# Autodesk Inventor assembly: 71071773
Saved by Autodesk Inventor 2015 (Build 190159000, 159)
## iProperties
Created: 2019-12
Part Number: 71071773
Checked By: TraceParts S.A.
Catalog Web Link: www.traceparts.com
Document SubType Name: Assembly
Designer: TraceParts
Company: TraceParts S.A.
Author: TraceParts
REFERENCE: 61303211821
SUPPLIER: Wurth Elektronik
ALLIED_STOCK_NUMBER: 71071773
DESIGN: WR-PHD 2.54 mm Socket Header,  32 pins
TraceParts.PartVersion: 1.0.2
TraceParts.PartStatus: Published
TraceParts.PartNumber: 10-11012018-134406
TraceParts.PartLanguage: en
TraceParts.InstanceId: 10-11012018-1344062D2ZSOQCMNYJ24BQHMF4MKBWH
TraceParts.PartTitle: WR-PHD 2.54 mm Socket Header,  32 pins
TRACEPARTS: TRACEPARTS
TraceParts.ClassPath: ALLIED_ELECTRONICS:/ALLIED_ELECTRONICS/PSSS_435563/PSS_435683/PSF_435704/10-11012018-134406
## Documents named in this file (34)
- C:\TPO v2\SharedFS\Outgoing\71071773.iam
- C:\TPO v2\SharedFS\Outgoing\71071773_01.ipt
- C:\TPO v2\SharedFS\Outgoing\71071773_02.ipt
- C:\TPO v2\SharedFS\Outgoing\71071773_03.ipt
- C:\TPO v2\SharedFS\Outgoing\71071773_04.ipt
- C:\TPO v2\SharedFS\Outgoing\71071773_05.ipt
- C:\TPO v2\SharedFS\Outgoing\71071773_06.ipt
- C:\TPO v2\SharedFS\Outgoing\71071773_07.ipt
- C:\TPO v2\SharedFS\Outgoing\71071773_08.ipt
- C:\TPO v2\SharedFS\Outgoing\71071773_09.ipt
- C:\TPO v2\SharedFS\Outgoing\71071773_10.ipt
- C:\TPO v2\SharedFS\Outgoing\71071773_11.ipt
- C:\TPO v2\SharedFS\Outgoing\71071773_12.ipt
- C:\TPO v2\SharedFS\Outgoing\71071773_13.ipt
- C:\TPO v2\SharedFS\Outgoing\71071773_14.ipt
- C:\TPO v2\SharedFS\Outgoing\71071773_15.ipt
- C:\TPO v2\SharedFS\Outgoing\71071773_16.ipt
- C:\TPO v2\SharedFS\Outgoing\71071773_17.ipt
- C:\TPO v2\SharedFS\Outgoing\71071773_18.ipt
- C:\TPO v2\SharedFS\Outgoing\71071773_19.ipt
- C:\TPO v2\SharedFS\Outgoing\71071773_20.ipt
- C:\TPO v2\SharedFS\Outgoing\71071773_21.ipt
- C:\TPO v2\SharedFS\Outgoing\71071773_22.ipt
- C:\TPO v2\SharedFS\Outgoing\71071773_23.ipt
- C:\TPO v2\SharedFS\Outgoing\71071773_24.ipt
- C:\TPO v2\SharedFS\Outgoing\71071773_25.ipt
- C:\TPO v2\SharedFS\Outgoing\71071773_26.ipt
- C:\TPO v2\SharedFS\Outgoing\71071773_27.ipt
- C:\TPO v2\SharedFS\Outgoing\71071773_28.ipt
- C:\TPO v2\SharedFS\Outgoing\71071773_29.ipt
- C:\TPO v2\SharedFS\Outgoing\71071773_30.ipt
- C:\TPO v2\SharedFS\Outgoing\71071773_31.ipt
- C:\TPO v2\SharedFS\Outgoing\71071773_32.ipt
- C:\TPO v2\SharedFS\Outgoing\71071773_33.ipt
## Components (33 placed, 33 different names)
1. 71071773_01:1
2. 71071773_02:1
3. 71071773_03:1
4. 71071773_04:1
5. 71071773_05:1
6. 71071773_06:1
7. 71071773_07:1
8. 71071773_08:1
9. 71071773_09:1
10. 71071773_10:1
11. 71071773_11:1
12. 71071773_12:1
13. 71071773_13:1
14. 71071773_14:1
15. 71071773_15:1
16. 71071773_16:1
17. 71071773_17:1
18. 71071773_18:1
19. 71071773_19:1
20. 71071773_20:1
21. 71071773_21:1
22. 71071773_22:1
23. 71071773_23:1
24. 71071773_24:1
25. 71071773_25:1
26. 71071773_26:1
27. 71071773_27:1
28. 71071773_28:1
29. 71071773_29:1
30. 71071773_30:1
31. 71071773_31:1
32. 71071773_32:1
33. 71071773_33:1
